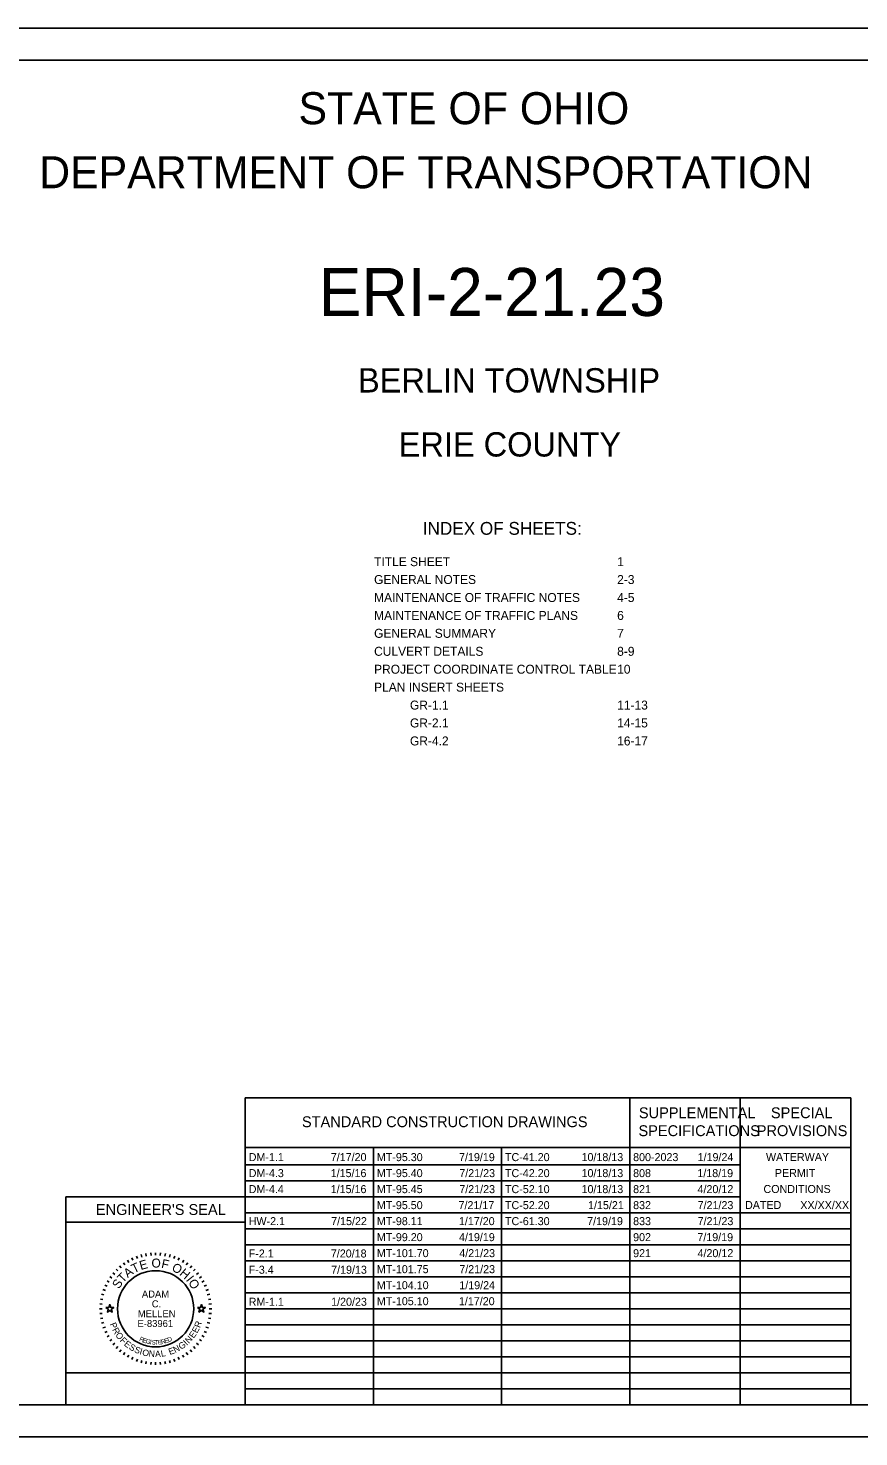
# Model space of a CAD drawing. Extents: x 0 to 34, y 0 to 22.
# Drawn here: x 9.58 to 22.54, y 0 to 22 of the extents above; entities that cross this region are included whole.
import ezdxf

# ---------------------------------------------------------------- set-up
doc = ezdxf.new("R2010")
doc.units = 0
for name, color, linetype in [('Default', 7, 'Continuous'), ('SH_Border', 7, 'Continuous'), ('SH_Cut_Line', 7, 'Continuous'), ('SH_Data', 7, 'Continuous'), ('SH_Text', 7, 'Continuous')]:
    doc.layers.add(name, color=color, linetype=linetype)

msp = doc.modelspace()

# ---------------------------------------------------------------- linework, layer by layer
at = {"layer": 'Default'}
for points in [[(10.789, 2.02), (10.836, 2.02), (10.85, 2.065), (10.865, 2.02), (10.912, 2.02), (10.874, 1.992), (10.888, 1.948), (10.85, 1.975), (10.812, 1.948), (10.827, 1.992)], [(12.219, 2.02), (12.266, 2.02), (12.28, 2.065), (12.295, 2.02), (12.342, 2.02), (12.304, 1.992), (12.318, 1.948), (12.28, 1.975), (12.242, 1.948), (12.257, 1.992)]]:
    msp.add_lwpolyline(points, close=True, dxfattribs=at)
at = {"layer": 'SH_Border'}
msp.add_lwpolyline([(1.5, 21.5), (33.5, 21.5), (33.5, 0.5), (1.5, 0.5)], close=True, dxfattribs=at)
at = {"layer": 'SH_Cut_Line'}
msp.add_lwpolyline([(0, 0), (34, 0), (34, 22), (0, 22)], close=True, dxfattribs=at)
at = {"layer": 'SH_Data'}
for p, q in [((12.965, 5.292), (22.415, 5.292)), ((12.965, 0.5), (12.965, 5.292)), ((18.965, 0.5), (18.965, 5.292)), ((20.69, 0.5), (20.69, 5.292)), ((22.415, 0.5), (22.415, 5.292)), ((12.965, 4.521), (22.415, 4.521)), ((14.965, 0.5), (14.965, 4.521)), ((16.965, 0.5), (16.965, 4.521)), ((18.965, 0.5), (18.965, 4.521)), ((12.965, 4.25), (20.69, 4.25)), ((12.965, 4), (20.69, 4)), ((12.965, 3.75), (10.165, 3.75)), ((10.165, 3.75), (10.165, 0.5)), ((12.965, 3.75), (20.69, 3.75)), ((12.965, 0.5), (12.965, 3.75)), ((12.965, 3.35), (10.165, 3.35)), ((12.965, 3.5), (22.415, 3.5)), ((12.965, 3.25), (22.415, 3.25)), ((11.413, 2.862), (11.42, 2.822)), ((11.489, 2.872), (11.493, 2.832)), ((11.565, 2.875), (11.565, 2.835)), ((11.642, 2.872), (11.638, 2.832)), ((11.717, 2.862), (11.71, 2.822)), ((12.965, 3), (22.415, 3)), ((11.003, 2.67), (11.029, 2.64)), ((11.063, 2.717), (11.086, 2.684)), ((11.128, 2.758), (11.148, 2.723)), ((11.195, 2.793), (11.212, 2.757)), ((11.266, 2.822), (11.28, 2.785)), ((11.339, 2.845), (11.349, 2.807)), ((11.792, 2.845), (11.781, 2.807)), ((11.865, 2.822), (11.851, 2.785)), ((11.935, 2.793), (11.918, 2.757)), ((12.003, 2.758), (11.983, 2.723)), ((12.067, 2.717), (12.044, 2.684)), ((12.128, 2.67), (12.102, 2.64)), ((12.965, 2.75), (22.415, 2.75)), ((10.808, 2.438), (10.842, 2.418)), ((10.849, 2.502), (10.881, 2.479)), ((10.895, 2.562), (10.926, 2.537)), ((10.947, 2.619), (10.975, 2.59)), ((12.184, 2.619), (12.156, 2.59)), ((12.236, 2.562), (12.205, 2.537)), ((12.282, 2.502), (12.249, 2.479)), ((12.323, 2.438), (12.288, 2.418)), ((12.965, 2.5), (22.415, 2.5)), ((10.72, 2.226), (10.759, 2.216)), ((10.743, 2.299), (10.781, 2.286)), ((10.772, 2.37), (10.809, 2.353)), ((12.358, 2.37), (12.322, 2.353)), ((12.388, 2.299), (12.35, 2.286)), ((12.41, 2.226), (12.372, 2.216)), ((12.965, 2.25), (22.415, 2.25)), ((10.69, 2), (10.73, 2)), ((10.694, 2.076), (10.733, 2.073)), ((10.704, 2.152), (10.743, 2.145)), ((12.427, 2.152), (12.388, 2.145)), ((12.437, 2.076), (12.397, 2.073)), ((12.44, 2), (12.4, 2)), ((12.965, 2), (22.415, 2)), ((10.694, 1.924), (10.733, 1.927)), ((10.704, 1.848), (10.743, 1.855)), ((10.72, 1.774), (10.759, 1.784)), ((12.41, 1.774), (12.372, 1.784)), ((12.427, 1.848), (12.388, 1.855)), ((12.437, 1.924), (12.397, 1.927)), ((10.743, 1.701), (10.781, 1.714)), ((10.772, 1.63), (10.809, 1.647)), ((10.808, 1.563), (10.842, 1.583)), ((12.323, 1.563), (12.288, 1.583)), ((12.358, 1.63), (12.322, 1.647)), ((12.388, 1.701), (12.35, 1.714)), ((12.965, 1.75), (22.415, 1.75)), ((10.849, 1.498), (10.881, 1.521)), ((10.895, 1.438), (10.926, 1.463)), ((10.947, 1.381), (10.975, 1.41)), ((11.003, 1.33), (11.029, 1.36)), ((12.128, 1.33), (12.102, 1.36)), ((12.184, 1.381), (12.156, 1.41)), ((12.236, 1.438), (12.205, 1.463)), ((12.282, 1.498), (12.249, 1.521)), ((12.965, 1.5), (22.415, 1.5)), ((11.063, 1.283), (11.086, 1.316)), ((11.128, 1.242), (11.148, 1.277)), ((11.195, 1.207), (11.212, 1.243)), ((11.266, 1.178), (11.28, 1.215)), ((11.339, 1.155), (11.349, 1.193)), ((11.413, 1.138), (11.42, 1.178)), ((11.489, 1.128), (11.493, 1.168)), ((11.565, 1.125), (11.565, 1.165)), ((11.642, 1.128), (11.638, 1.168)), ((11.717, 1.138), (11.71, 1.178)), ((11.792, 1.155), (11.781, 1.193)), ((11.865, 1.178), (11.851, 1.215)), ((11.935, 1.207), (11.918, 1.243)), ((12.003, 1.242), (11.983, 1.277)), ((12.067, 1.283), (12.044, 1.316)), ((12.965, 1.25), (22.415, 1.25)), ((12.965, 1), (22.415, 1)), ((12.965, 0.75), (22.415, 0.75)), ((12.965, 0.5), (10.165, 0.5))]:
    msp.add_line(p, q, dxfattribs=at)
msp.add_lwpolyline([(12.965, 0.5), (12.965, 1), (10.165, 1), (10.165, 0.5)], close=True, dxfattribs=at)
msp.add_circle((11.565, 2), 0.595, dxfattribs=at)

# ---------------------------------------------------------------- texts
for s, height, p in [("ENGINEER'S SEAL", 0.17, (10.633, 3.465)), ('ADAM', 0.11, (11.351, 2.175)), ('C.', 0.11, (11.505, 2.022)), ('E-83961', 0.11, (11.282, 1.715)), ('MELLEN', 0.11, (11.287, 1.868))]:
    msp.add_text(s, height=height, dxfattribs=at).set_placement(p)
for s, height, rotation, p in [('T', 0.14, 25.7167, (11.227, 2.552)), ('E', 0.14, 15.7571, (11.334, 2.604)), ('O', 0.14, 359.7812, (11.5, 2.644)), ('F', 0.14, 347.4362, (11.646, 2.642)), ('O', 0.14, 332.2586, (11.805, 2.602)), ('S', 0.14, 57.1924, (10.993, 2.301)), ('T', 0.14, 46.4344, (11.054, 2.396)), ('A', 0.14, 36.4747, (11.129, 2.478)), ('H', 0.14, 319.9136, (11.928, 2.536)), ('I', 0.14, 308.367, (12.032, 2.448)), ('O', 0.14, 303.1491, (12.067, 2.409)), ('P', 0.1, 291.494, (10.848, 1.762)), ('R', 0.1, 69.2322, (12.257, 1.695)), ('R', 0.1, 298.7311, (10.884, 1.672)), ('O', 0.1, 306.4666, (10.931, 1.588)), ('F', 0.1, 314.7068, (11, 1.498)), ('R', 0.07, 334.487, (11.303, 1.505)), ('E', 0.07, 341.04, (11.356, 1.48)), ('E', 0.07, 17.6836, (11.715, 1.46)), ('D', 0.07, 23.3052, (11.766, 1.477)), ('N', 0.1, 47.0224, (12.085, 1.451)), ('E', 0.1, 54.758, (12.159, 1.531)), ('E', 0.1, 61.9951, (12.213, 1.61)), ('E', 0.1, 321.4393, (11.063, 1.435)), ('S', 0.1, 328.6764, (11.14, 1.375)), ('S', 0.1, 335.9134, (11.222, 1.327)), ('I', 0.1, 343.1505, (11.306, 1.29)), ('O', 0.1, 346.8859, (11.349, 1.275)), ('G', 0.07, 347.4752, (11.407, 1.462)), ('N', 0.1, 355.1261, (11.454, 1.252)), ('I', 0.07, 353.7858, (11.474, 1.447)), ('S', 0.07, 356.8926, (11.501, 1.443)), ('T', 0.07, 3.0061, (11.551, 1.439)), ('A', 0.1, 2.8617, (11.558, 1.244)), ('E', 0.07, 6.0117, (11.604, 1.441)), ('L', 0.1, 10.0987, (11.655, 1.249)), ('R', 0.07, 11.9184, (11.658, 1.447)), ('E', 0.1, 20.0742, (11.787, 1.277)), ('N', 0.1, 27.3113, (11.87, 1.308)), ('G', 0.1, 35.0469, (11.963, 1.357)), ('I', 0.1, 43.287, (12.052, 1.421))]:
    msp.add_text(s, height=height, rotation=rotation, dxfattribs=at).set_placement(p)
at = {"layer": 'SH_Text'}
for s, height, p in [('STATE OF OHIO', 0.5, (13.795, 20.5)), ('DEPARTMENT OF TRANSPORTATION', 0.5, (9.747, 19.5)), ('ERI-2-21.23', 0.75, (14.109, 17.505)), ('BERLIN TOWNSHIP', 0.38, (14.724, 16.31)), ('ERIE COUNTY', 0.38, (15.358, 15.31)), ('INDEX OF SHEETS:', 0.2, (15.735, 14.088)), ('TITLE SHEET', 0.14, (14.975, 13.598)), ('1', 0.14, (18.769, 13.598)), ('GENERAL NOTES', 0.14, (14.975, 13.319)), ('2-3', 0.14, (18.769, 13.319)), ('MAINTENANCE OF TRAFFIC NOTES', 0.14, (14.975, 13.038)), ('4-5', 0.14, (18.769, 13.038)), ('MAINTENANCE OF TRAFFIC PLANS', 0.14, (14.975, 12.758)), ('6', 0.14, (18.769, 12.758)), ('GENERAL SUMMARY', 0.14, (14.975, 12.479)), ('7', 0.14, (18.769, 12.479)), ('CULVERT DETAILS', 0.14, (14.975, 12.198)), ('8-9', 0.14, (18.769, 12.198)), ('PROJECT COORDINATE CONTROL TABLE', 0.14, (14.975, 11.918)), ('10', 0.14, (18.769, 11.918)), ('PLAN INSERT SHEETS', 0.14, (14.975, 11.638)), ('GR-1.1', 0.14, (15.535, 11.358)), ('11-13', 0.14, (18.769, 11.358)), ('GR-2.1', 0.14, (15.535, 11.079)), ('14-15', 0.14, (18.769, 11.079)), ('GR-4.2', 0.14, (15.535, 10.798)), ('16-17', 0.14, (18.769, 10.798)), ('SUPPLEMENTAL', 0.17, (19.108, 4.976)), ('SPECIAL', 0.17, (21.169, 4.976)), ('STANDARD CONSTRUCTION DRAWINGS', 0.17, (13.849, 4.836)), ('SPECIFICATIONS', 0.17, (19.102, 4.696)), ('PROVISIONS', 0.17, (20.948, 4.696)), ('DM-1.1', 0.125, (13.018, 4.306)), ('7/17/20', 0.125, (14.299, 4.306)), ('MT-95.30', 0.125, (15.018, 4.306)), ('7/19/19', 0.125, (16.301, 4.306)), ('TC-41.20', 0.125, (17.018, 4.306)), ('10/18/13', 0.125, (18.213, 4.306)), ('800-2023', 0.125, (19.018, 4.306)), ('1/19/24', 0.125, (20.025, 4.306)), ('WATERWAY', 0.125, (21.092, 4.308)), ('DM-4.3', 0.125, (13.018, 4.056)), ('1/15/16', 0.125, (14.298, 4.056)), ('MT-95.40', 0.125, (15.018, 4.056)), ('7/21/23', 0.125, (16.305, 4.056)), ('TC-42.20', 0.125, (17.018, 4.056)), ('10/18/13', 0.125, (18.213, 4.056)), ('808', 0.125, (19.018, 4.056)), ('1/18/19', 0.125, (20.021, 4.056)), ('PERMIT', 0.125, (21.231, 4.058)), ('DM-4.4', 0.125, (13.018, 3.806)), ('1/15/16', 0.125, (14.298, 3.806)), ('MT-95.45', 0.125, (15.018, 3.806)), ('7/21/23', 0.125, (16.305, 3.806)), ('TC-52.10', 0.125, (17.018, 3.806)), ('10/18/13', 0.125, (18.213, 3.806)), ('821', 0.125, (19.018, 3.806)), ('4/20/12', 0.125, (20.024, 3.806)), ('CONDITIONS', 0.125, (21.053, 3.808)), ('MT-95.50', 0.125, (15.018, 3.556)), ('7/21/17', 0.125, (16.293, 3.556)), ('TC-52.20', 0.125, (17.018, 3.556)), ('1/15/21', 0.125, (18.315, 3.556)), ('832', 0.125, (19.018, 3.556)), ('7/21/23', 0.125, (20.025, 3.556)), ('DATED', 0.125, (20.765, 3.558)), ('XX/XX/XX', 0.125, (21.628, 3.556)), ('HW-2.1', 0.125, (13.018, 3.306)), ('7/15/22', 0.125, (14.305, 3.306)), ('MT-98.11', 0.125, (15.018, 3.306)), ('1/17/20', 0.125, (16.299, 3.306)), ('TC-61.30', 0.125, (17.018, 3.306)), ('7/19/19', 0.125, (18.301, 3.306)), ('833', 0.125, (19.018, 3.306)), ('7/21/23', 0.125, (20.025, 3.306)), ('MT-99.20', 0.125, (15.018, 3.056)), ('4/19/19', 0.125, (16.301, 3.056)), ('902', 0.125, (19.018, 3.056)), ('7/19/19', 0.125, (20.021, 3.056)), ('F-2.1', 0.125, (13.018, 2.801)), ('7/20/18', 0.125, (14.3, 2.801)), ('MT-101.70', 0.125, (15.018, 2.806)), ('4/21/23', 0.125, (16.305, 2.806)), ('921', 0.125, (19.018, 2.806)), ('4/20/12', 0.125, (20.024, 2.806)), ('F-3.4', 0.125, (13.018, 2.547)), ('7/19/13', 0.125, (14.305, 2.547)), ('MT-101.75', 0.125, (15.018, 2.556)), ('7/21/23', 0.125, (16.305, 2.556)), ('MT-104.10', 0.125, (15.018, 2.306)), ('1/19/24', 0.125, (16.305, 2.306)), ('RM-1.1', 0.125, (13.018, 2.047)), ('1/20/23', 0.125, (14.305, 2.047)), ('MT-105.10', 0.125, (15.018, 2.056)), ('1/17/20', 0.125, (16.299, 2.056))]:
    msp.add_text(s, height=height, dxfattribs=at).set_placement(p)

doc.saveas('drawing.dxf')
